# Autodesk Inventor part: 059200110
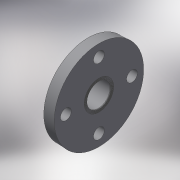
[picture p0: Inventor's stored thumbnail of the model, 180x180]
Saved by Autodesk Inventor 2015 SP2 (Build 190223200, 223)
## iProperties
Created: 2017-10
Part Number: 059200110
Material: Generic
Description: PLASSON FIXED FLANGE-CEM PVC 110
Document SubType Name: Modeling
Designer: KIM
Mass: 751.802 g
Surface Area: 1188.68 cm^2
Volume: 751.802 cm^3
Density: 1 g/cm^3
Appearance: Default
Author: KIM
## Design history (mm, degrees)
derived "059200.ipt"
feature "Solid1::059200.ipt"
tag "TaggingFeature1"
body "Solid1"
other parameters: "d0" = 64, "d3" = 217.8, "d14" = 18, "d16" = 64, "d17" = 0, "d19" = 360 deg, "d21" = 61, "d23" = 104.5, "d24" = 132, "d25" = 1.1, "d26" = 1.1, "d27" = 1.1, "d28" = 1.1, "d29" = 1.1, "d30" = 1.1, "d31" = 1.1, "d32" = 0.44, "d33" = 0, "d34" = 22, "H_" = 64, "S_" = 18, "l_" = 61, "H_1" = 22
